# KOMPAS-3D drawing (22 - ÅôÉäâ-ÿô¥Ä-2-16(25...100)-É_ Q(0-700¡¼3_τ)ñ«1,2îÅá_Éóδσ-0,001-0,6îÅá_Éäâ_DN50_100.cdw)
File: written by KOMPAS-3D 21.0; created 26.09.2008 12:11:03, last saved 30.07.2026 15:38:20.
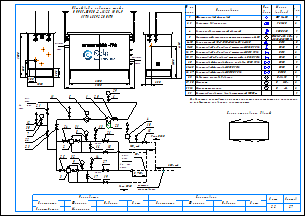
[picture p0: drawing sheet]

Sheets 1-2: A3, landscape

Document properties: Наименование: Макро:21; Автор: RaskoAdmin; Форматы листов документа: 2xA3; Полное имя файла: \\ur38nt01\Departments\КТО\КБ ПУРДГ\Заявки\Прайс-лист на типовые шкафы ГРПШ\ПУРДГ_стандарт_30_04_2026\ПУРДГ с РДГ(Н, В)\ПУРДГ-ШУЭО-2-16(25...100)-Р_ Q(0-700нм3_ч)до1,2МПа_Рвых-0,001-0,6МПа_РДГ_DN50_100.cdw

Title block, sheet 1: Наименование: Пункт учета газа / ПУГ-Ш-400-Р / ЛГТИ.485922.001ТУ; designation: ЛГТИ.03.4411141; sheet number: 1; Количество листов документа: 2; organisation: ООО "ЭЛЬСТЕР Газэлектроника"; Форматы листов документа: A3; stored path: C:\Рабочие документы\Компас\ПУГ\Схема.cdw; Разработал: Устинов; Проверил: Кошкин; Утвердил: Кошкин
Title block, sheet 2: sheet number: 2; stored path: D:\Рабочие документы\Заявки\ПУРДГ\ПУРДГ-ШУЭО-2-100-Р 4411220.cdw; designation, second copy: ЛГТИ.03.4411141-

Views: Вид 1, Вид 2
Referenced files: wcvoit.frw
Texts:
  Normal
  № на
  схеме
  Усл.
  обозн.
  Марка
  (модель)
  Кол.
  Фильтр газовый фланцевый
  ФГ 16-50
  Регулятор давления газа
  РДГ-50
  Клапан предохранительный сбросной
  КПС DN20
  Измерительный комплекс с ротационным счетчиком Ду50
  СГ-ЭК-Р-(0,2...2,0)-
  Кран кнопочный VE-РАСКО-НЗ-1,6-G1/2-М20
  DN15
  Кран шаровой "под приварку" штуцерный DN20 PN16
  DN20
  Кран шаровой "под приварку" штуцерный DN15 PN16
  Кран шаровой "под приварку" штуцерный п/п DN20 PN16
  Кран шаровой фланцевый с мех. приводом DN50 PN16
  Кран шаровой фланцевый DN50 PN16
  Кран шаровой фланцевый DN100 PN16
  DN50
  DN100
  Индикатор перепада давления
  Манометр
  Манометр-напоромер
  Электрообогреватель взрывозащищенный 1000Вт
  Delta 15
  0...     МПа
  0...     кПа
  Общий вид и габариты шкафа
  ПУРДГ-ШУЭО-2-16(25...100)-Р
  Выход газа
  Вход газа
  logo-rasko-ge.png
  DN 1
  местное
  сопротивление
  Римп DN20
  Выход
  газа
  Р=     кПа
  Вход
  Р=       МПа
  PDI
  Схема открывания дверей
  Предприятие изготовитель может заменять комплектующие на аналогичные,
  не ухудшающие заявленных характеристик.
  Должность
  Конструктор
  Фамилия
  Подпись
  Дата
  Согласовано
  Максимкин
  Лист
  Листов
  POLYLINE_STYLE_0.18_RGB_0_0_0
  POLYLINE_STYLE_0.50_RGB_0_0_0
  POLYLINE_STYLE_0.34_RGB_0_0_0
  PHANTOM_RGB_0_0_0_SC_1_THICK_0.18
  K5LT_THIN_RGB_0_0_0_THICK_0.18
  K5LT32769_RGB_0_0_0_THICK_0.18
  K5LT12_RGB_0_0_0_SC_1_THICK_0.18
  K5LT_DASHED_RGB_0_0_0_SC_1_THICK_0.18
  ACISOTGL_RGB_0_0_0_SC_0.8_THICK_0.25
  CONTINUOUS_RGB_0_127_31_THICK_0.3
  CONTINUOUS_RGB_0_0_255_THICK_0.35
  CONTINUOUS_RGB_255_0_0_THICK_0.35
  POLYLINE_STYLE_0.25_RGB_0_0_0
  CONTINUOUS_RGB_0_0_0_THICK_0.5
  POLYLINE_STYLE_0.35_RGB_0_0_255
  CONTINUOUS_RGB_0_0_0_THICK_0.4
  CONTINUOUS_RGB_0_0_0_THICK_0.35
  НЕВИДИМАЯ_RGB_0_0_0_SC_0.3_THICK_0.25
  СONTINUOUS_RGB_0_0_0_THICK_0.25
  ОСЕВАЯ2_RGB_248_153_30_SC_0.3_THICK_0.25
  Без оформления
Dimensions and other numbers on the sheet: 1; 2, 3; 2; 4; 5; 6-10; 11-15; 16, 17; 18, 19; 20; 21-25; 26, 27; 28; 29, 30; 31, 32; 33; 1500; 250; 300; 1050; 550; 305; 2800; 4130; 2000; 3100; 5,,,7DN 1; 7; 30; 12; 21; 22; 23; 11; 6; 29; 24; 31; 8; 13; 26; 18; 10; 15; 25; 32; 9; 3; 14; 27; 19; 16; 17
